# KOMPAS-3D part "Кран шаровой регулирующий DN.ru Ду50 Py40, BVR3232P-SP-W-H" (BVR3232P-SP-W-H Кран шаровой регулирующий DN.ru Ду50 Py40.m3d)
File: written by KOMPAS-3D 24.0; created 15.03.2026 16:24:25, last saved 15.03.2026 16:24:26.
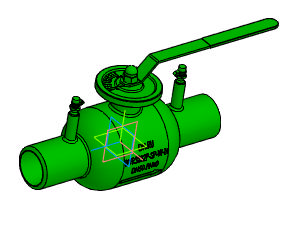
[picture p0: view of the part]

Document properties: Автор: Максим; Полное имя файла: D:\Rabota ebanaya\BVR3232P-SP-W-H Кран шаровой регулирующий Ду15-150\Типоразмеры\DN50\BVR3232P-SP-W-H Кран шаровой регулирующий DN.ru Ду50 Py40.m3d

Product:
- Body: Тело 1  | qty 1
    Масса: 10.894412
- Part/product: Кран шаровой регулирующий DN.ru Ду50 Py40  | designation BVR3232P-SP-W-H
    Масса: 5.3
    Раздел спецификации: Прочие изделия
    Форматы листов документа: D160-28455

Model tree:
1. Операция без истории:1

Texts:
  BVR3232P-SP-W-H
